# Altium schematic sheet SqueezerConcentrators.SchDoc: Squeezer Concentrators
size C; Organization: LIGO Laboratory; Address1: California Institute of Technology; Address2: Massachusetts Institute of Technology; SheetNumber: 34; SheetTotal: 37; DrawnBy: R.  Abbott; Engineer: R.  Abbott; PageSetup: Record=PageOptions¦CenterHorizontal=True¦CenterVertical=True¦PrintScale=1.09¦XCorrection=1.00¦YCorrection=1.00¦PrintKind=0¦BorderSize=5000000¦LeftOffset=0¦BottomOffset=0¦Orientation=2¦PaperLength=1000¦PaperWidth=1000¦Scale=100¦PaperSource=7¦PrintQuality=-4¦MediaType=1¦DitherType=10¦PaperKind=11x17¦PrintScaleMode=1
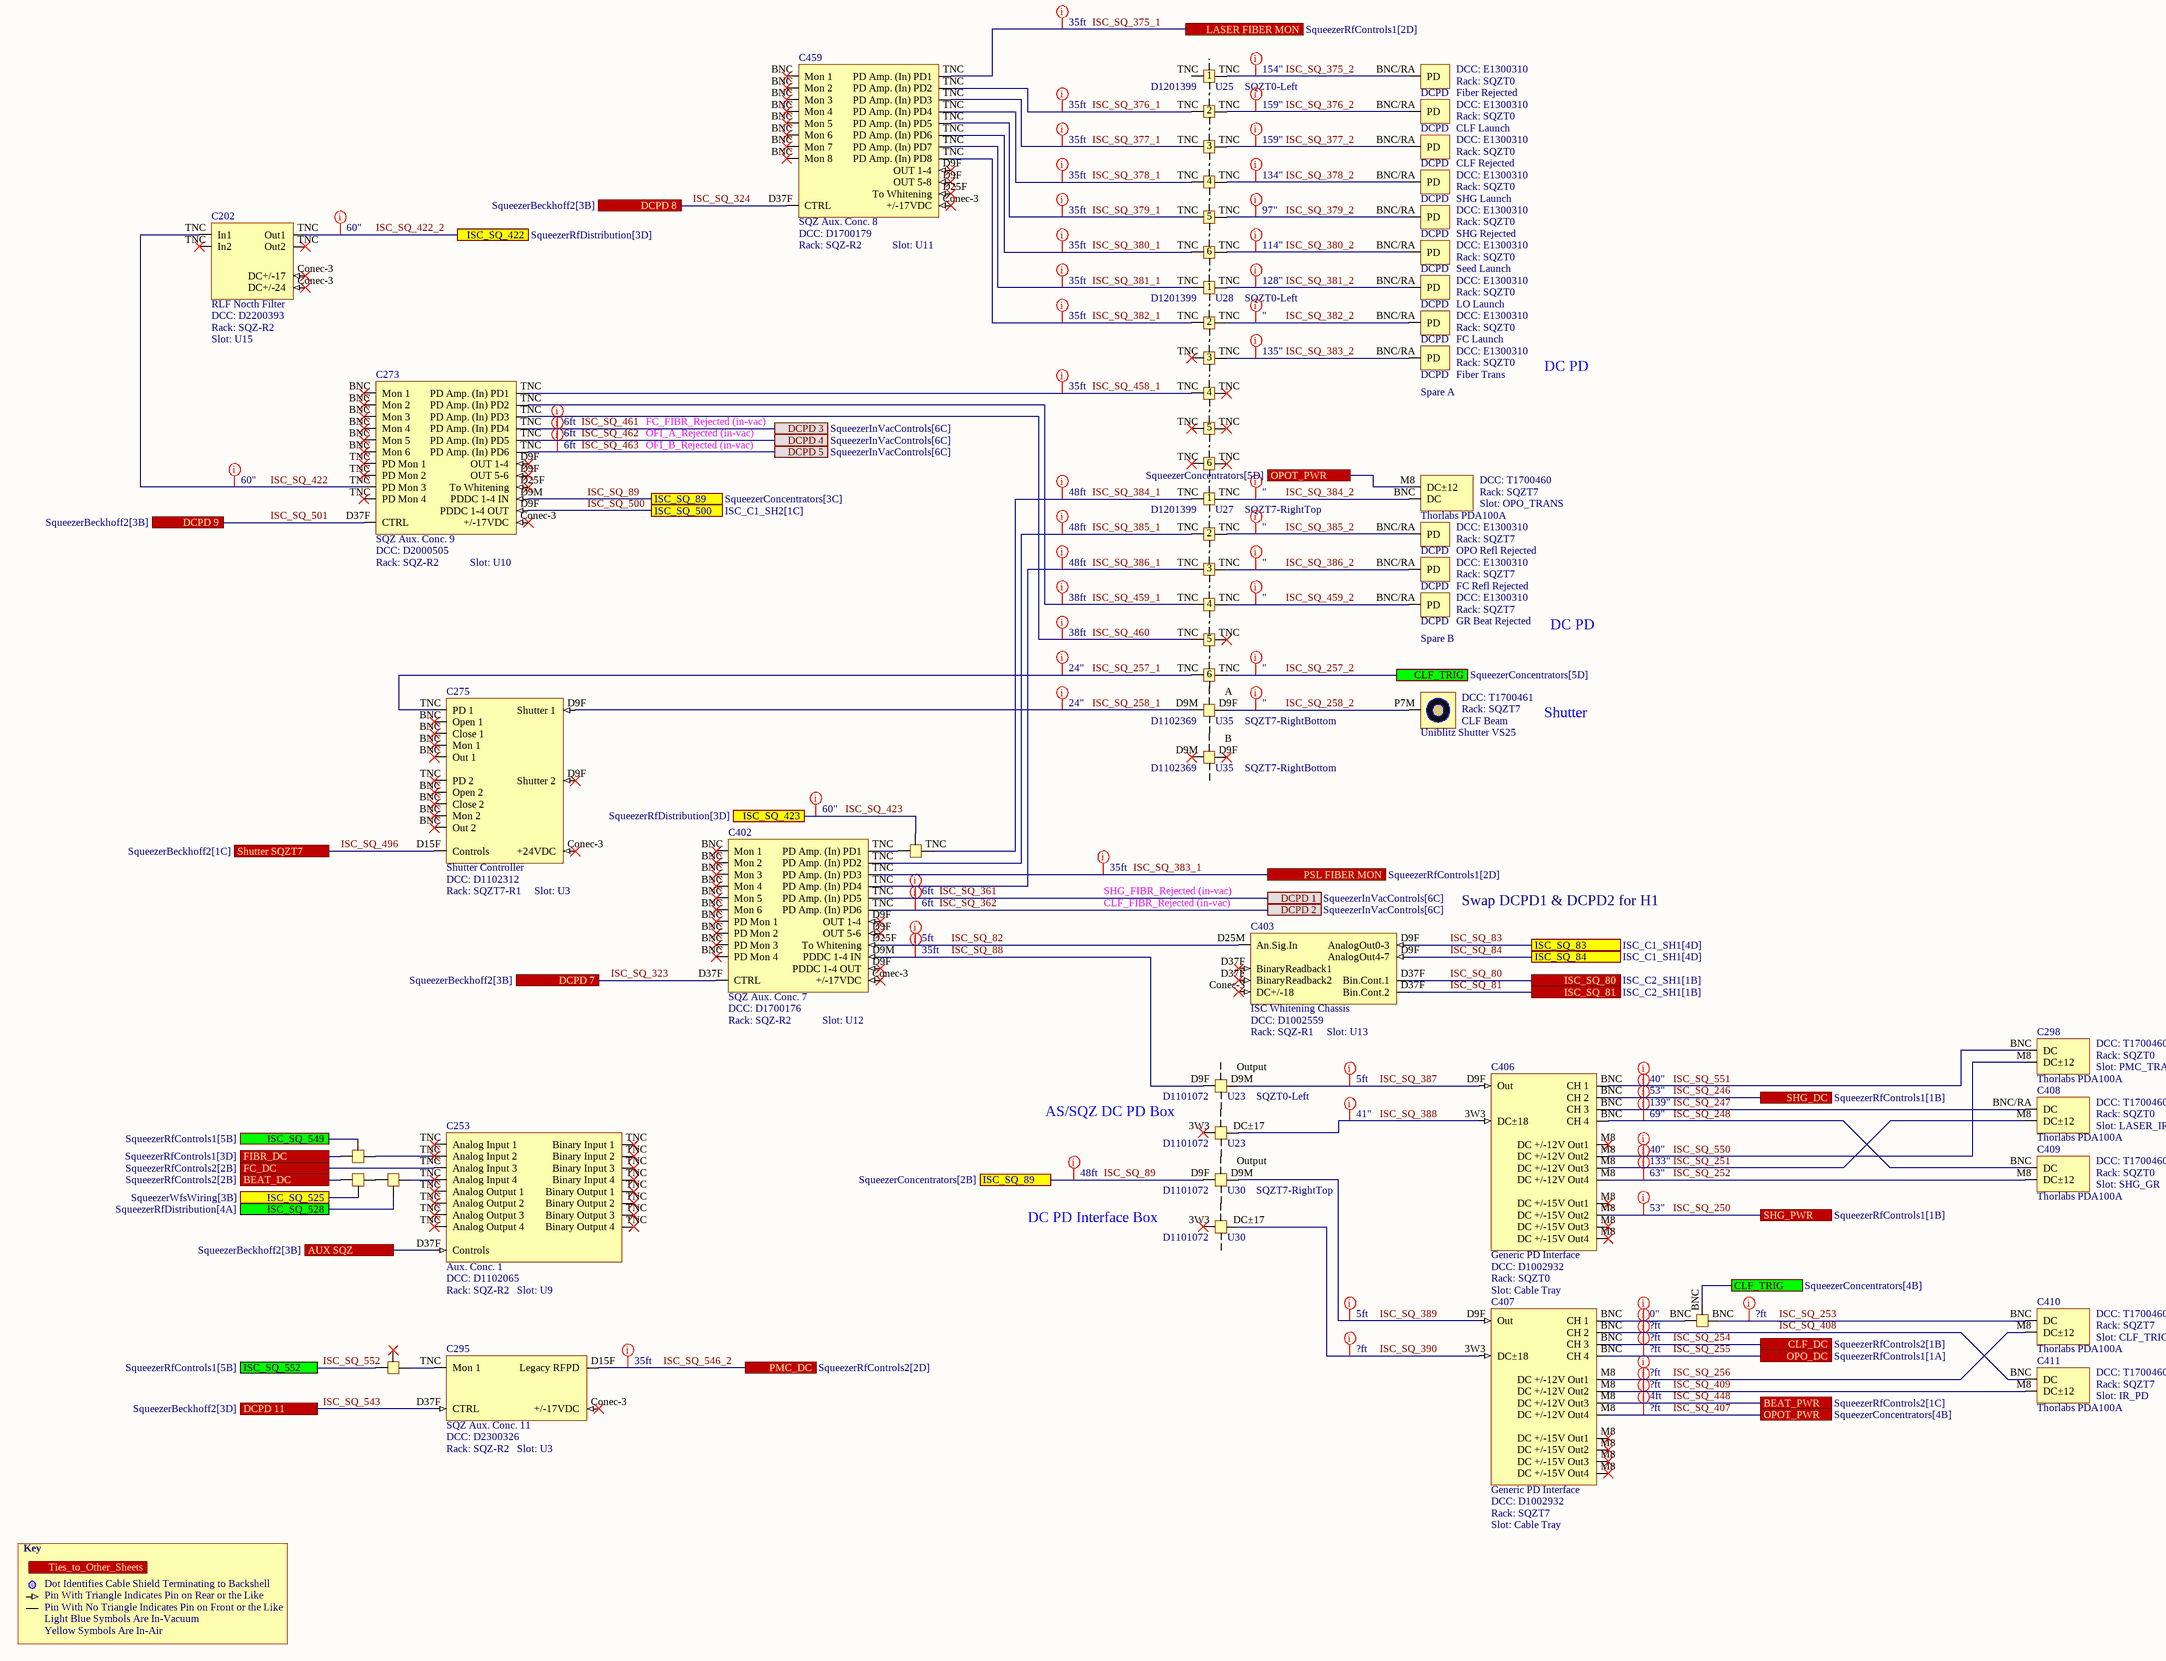
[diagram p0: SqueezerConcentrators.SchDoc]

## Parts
C202  RLF Nocth Filter  DCC: D2200393  Rack: SQZ-R2  Slot: U15
C235  DCPD  DCC: E1300310  Rack: SQZT0  Slot: FC Launch
C253  Aux. Conc. 1  DCC: D1102065  Rack: SQZ-R2  Slot: U9
C255  DCPD  DCC: E1300310  Rack: SQZT7  Slot: FC Refl Rejected
C256  DCPD  DCC: E1300310  Rack: SQZT7  Slot: GR Beat Rejected
C271  Tee  (value not drawn)
C273  SQZ Aux. Conc. 9  DCC: D2000505  Rack: SQZ-R2  Slot: U10
C275  Shutter Controller  DCC: D1102312  Rack: SQZT7-R1  Slot: U3
C283  Tee  (value not drawn)
C284  Tee  (value not drawn)
C295  SQZ Aux. Conc. 11  DCC: D2300326  Rack: SQZ-R2  Slot: U3
C297  Tee  (value not drawn)
C298  Thorlabs PDA100A  DCC: T1700460  Rack: SQZT0  Slot: PMC_TRANS
C315  Tee  (value not drawn)
C387  DCC: D1201399  Rack: SQZT0-Left  Slot: U25  (hidden comment: Patch Panel DCPD)  (parts A,B,C,D,E,F of 6)
C388  DCC: D1201399  Rack: SQZT0-Left  Slot: U28  (hidden comment: Patch Panel DCPD)  (parts A,B,C,D,E,F of 6)
C389  DCC: D1201399  Rack: SQZT7-RightTop  Slot: U27  (hidden comment: Patch Panel DCPD)  (parts A,B,C,D,E,F of 6)
C390  DCC: D1102369  Rack: SQZT7-RightBottom  Slot: U35  (hidden comment: Patch Panel Uniblitz Shutters)  (parts A,B of 2)
C391  DCPD  DCC: E1300310  Rack: SQZT0  Slot: Fiber Rejected
C392  DCPD  DCC: E1300310  Rack: SQZT0  Slot: CLF Launch
C393  DCPD  DCC: E1300310  Rack: SQZT0  Slot: CLF Rejected
C394  DCPD  DCC: E1300310  Rack: SQZT0  Slot: SHG Launch
C395  DCPD  DCC: E1300310  Rack: SQZT0  Slot: SHG Rejected
C396  DCPD  DCC: E1300310  Rack: SQZT0  Slot: Seed Launch
C397  DCPD  DCC: E1300310  Rack: SQZT0  Slot: LO Launch
C398  DCPD  DCC: E1300310  Rack: SQZT0  Slot: Fiber Trans
C399  Thorlabs PDA100A  DCC: T1700460  Rack: SQZT7  Slot: OPO_TRANS
C400  DCPD  DCC: E1300310  Rack: SQZT7  Slot: OPO Refl Rejected
C401  Uniblitz Shutter VS25  DCC: T1700461  Rack: SQZT7  Slot: CLF Beam
C402  SQZ Aux. Conc. 7  DCC: D1700176  Rack: SQZ-R2  Slot: U12
C403  ISC Whitening Chassis  DCC: D1002559  Rack: SQZ-R1  Slot: U13
C404  DCC: D1101072  Rack: SQZT0-Left  Slot: U23  (hidden comment: Patch Panel DCPD Interface)  (parts A,B of 2)
C405  DCC: D1101072  Rack: SQZT7-RightTop  Slot: U30  (hidden comment: Patch Panel DCPD Interface)  (parts A,B of 2)
C406  Generic PD Interface  DCC: D1002932  Rack: SQZT0  Slot: Cable Tray
C407  Generic PD Interface  DCC: D1002932  Rack: SQZT7  Slot: Cable Tray
C408  Thorlabs PDA100A  DCC: T1700460  Rack: SQZT0  Slot: LASER_IR
C409  Thorlabs PDA100A  DCC: T1700460  Rack: SQZT0  Slot: SHG_GR
C410  Thorlabs PDA100A  DCC: T1700460  Rack: SQZT7  Slot: CLF_TRIG
C411  Thorlabs PDA100A  DCC: T1700460  Rack: SQZT7  Slot: IR_PD
C459  SQZ Aux. Conc. 8  DCC: D1700179  Rack: SQZ-R2  Slot: U11
C467  Tee  (value not drawn)

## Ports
AUX SQZ (see SqueezerBeckhoff2[3B]), BEAT_DC (see SqueezerRfControls2[2B]), BEAT_PWR (see SqueezerRfControls2[1C]), CLF_DC (see SqueezerRfControls2[1B]), CLF_TRIG (see SqueezerConcentrators[4B]), CLF_TRIG (see SqueezerConcentrators[5D]), DCPD 1 (see SqueezerInVacControls[6C]), DCPD 2 (see SqueezerInVacControls[6C]), DCPD 3 (see SqueezerInVacControls[6C]), DCPD 4 (see SqueezerInVacControls[6C]), DCPD 5 (see SqueezerInVacControls[6C]), DCPD 7 (see SqueezerBeckhoff2[3B]), DCPD 8 (see SqueezerBeckhoff2[3B]), DCPD 9 (see SqueezerBeckhoff2[3B]), DCPD 11 (see SqueezerBeckhoff2[3D]), FC_DC (see SqueezerRfControls2[2B]), FIBR_DC (see SqueezerRfControls1[3D]), ISC_SQ_80 (see ISC_C2_SH1[1B]), ISC_SQ_81 (see ISC_C2_SH1[1B]), ISC_SQ_83 (see ISC_C1_SH1[4D]), ISC_SQ_84 (see ISC_C1_SH1[4D]), ISC_SQ_89 (see SqueezerConcentrators[2B]), ISC_SQ_89 (see SqueezerConcentrators[3C]), ISC_SQ_422 (see SqueezerRfDistribution[3D]), ISC_SQ_423 (see SqueezerRfDistribution[3D]), ISC_SQ_500 (see ISC_C1_SH2[1C]), ISC_SQ_525 (see SqueezerWfsWiring[3B]), ISC_SQ_528 (see SqueezerRfDistribution[4A]), ISC_SQ_549 (see SqueezerRfControls1[5B]), ISC_SQ_552 (see SqueezerRfControls1[5B]), LASER FIBER MON (see SqueezerRfControls1[2D]), OPO_DC (see SqueezerRfControls1[1A]), OPOT_PWR (see SqueezerConcentrators[4B]), OPOT_PWR (see SqueezerConcentrators[5D]), PMC_DC (see SqueezerRfControls2[2D]), PSL FIBER MON (see SqueezerRfControls1[2D]), SHG_DC (see SqueezerRfControls1[1B]), SHG_PWR (see SqueezerRfControls1[1B]), Shutter SQZT7 (see SqueezerBeckhoff2[1C]), Ties_to_Other_Sheets

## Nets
AUX SQZ: C253.D37F(Controls) ; port AUX SQZ
BEAT_DC: C467.TNC ; port BEAT_DC
FC_DC: C253.TNC(Analog_Input_3) ; port FC_DC
FIBR_DC: C297.TNC ; port FIBR_DC
ISC_SQ_80: C403.D37F(BinaryReadback1) ; port ISC_SQ_80
ISC_SQ_81: C403.D37F(Bin.Cont.2) ; port ISC_SQ_81
ISC_SQ_82: C402.D25F(To_Whitening) C403.D25M(An.Sig.In)
ISC_SQ_83: C403.D9F(AnalogOut0-3) ; port ISC_SQ_83
ISC_SQ_84: C403.D9F(AnalogOut4-7) ; port ISC_SQ_84
ISC_SQ_88: C402.D9M(PDDC_1-4_IN) C404.D9F(Output)
ISC_SQ_89: C273.D9M(PDDC_1-4_IN) C405.D9F(Output) ; port ISC_SQ_89
ISC_SQ_246: C406.BNC(CH_2) ; port SHG_DC
ISC_SQ_247: C406.BNC(CH_3) C408.BNC/RA(DC)
ISC_SQ_248: C406.BNC(CH_4) C409.BNC(DC)
ISC_SQ_250: C406.M8(DC_+/-15V_Out2) ; port SHG_PWR
ISC_SQ_251: C406.M8(DC_+/-12V_Out3) C408.M8(DC±12)
ISC_SQ_252: C406.M8(DC_+/-12V_Out4) C409.M8(DC±12)
ISC_SQ_253: C271.BNC C410.BNC(DC)
ISC_SQ_254: C407.BNC(CH_3) ; port CLF_DC
ISC_SQ_255: C407.BNC(CH_4) ; port OPO_DC
ISC_SQ_256: C407.M8(DC_+/-12V_Out1) C410.M8(DC±12)
ISC_SQ_257_1: C275.TNC(PD_1) C389.TNC
ISC_SQ_257_2: C271.BNC C389.TNC ; port CLF_TRIG
ISC_SQ_258_1: C275.D9F(Shutter_1) C390.D9M(Output)
ISC_SQ_258_2: C390.D9F(Output) C401.P7M
ISC_SQ_323: C402.D37F(CTRL) ; port DCPD 7
ISC_SQ_324: C459.D37F(CTRL) ; port DCPD 8
ISC_SQ_361: C402.TNC(PD_Amp._(In)_PD5) ; port DCPD 1
ISC_SQ_362: C402.TNC(PD_Amp._(In)_PD6) ; port DCPD 2
ISC_SQ_375_1: C459.TNC(PD_Amp._(In)_PD1) ; port LASER FIBER MON
ISC_SQ_375_2: C387.TNC C391.BNC/RA(PD)
ISC_SQ_376_1: C387.TNC C459.TNC(PD_Amp._(In)_PD2)
ISC_SQ_376_2: C387.TNC C392.BNC/RA(PD)
ISC_SQ_377_1: C387.TNC C459.TNC(PD_Amp._(In)_PD3)
ISC_SQ_377_2: C387.TNC C393.BNC/RA(PD)
ISC_SQ_378_1: C387.TNC C459.TNC(PD_Amp._(In)_PD4)
ISC_SQ_378_2: C387.TNC C394.BNC/RA(PD)
ISC_SQ_379_1: C387.TNC C459.TNC(PD_Amp._(In)_PD5)
ISC_SQ_379_2: C387.TNC C395.BNC/RA(PD)
ISC_SQ_380_1: C387.TNC C459.TNC(PD_Amp._(In)_PD6)
ISC_SQ_380_2: C387.TNC C396.BNC/RA(PD)
ISC_SQ_381_1: C388.TNC C459.TNC(PD_Amp._(In)_PD7)
ISC_SQ_381_2: C388.TNC C397.BNC/RA(PD)
ISC_SQ_382_1: C388.TNC C459.TNC(PD_Amp._(In)_PD8)
ISC_SQ_382_2: C235.BNC/RA(PD) C388.TNC
ISC_SQ_383_1: C402.TNC(PD_Amp._(In)_PD3) ; port PSL FIBER MON
ISC_SQ_383_2: C388.TNC C398.BNC/RA(PD)
ISC_SQ_384_1: C283.TNC C389.TNC
ISC_SQ_384_2: C389.TNC C399.BNC(DC)
ISC_SQ_385_1: C389.TNC C402.TNC(PD_Amp._(In)_PD2)
ISC_SQ_385_2: C389.TNC C400.BNC/RA(PD)
ISC_SQ_386_1: C389.TNC C402.TNC(PD_Amp._(In)_PD4)
ISC_SQ_386_2: C255.BNC/RA(PD) C389.TNC
ISC_SQ_387: C404.D9M(Output) C406.D9F(Out)
ISC_SQ_388: C404.3W3(DC±17) C406.3W3(DC±18)
ISC_SQ_389: C405.D9M(Output) C407.D9F(Out)
ISC_SQ_390: C405.3W3(DC±17) C407.3W3(DC±18)
ISC_SQ_407: C399.M8(DC±12) C407.M8(DC_+/-12V_Out4) ; port OPOT_PWR
ISC_SQ_408: C407.BNC(CH_2) C411.BNC(DC)
ISC_SQ_409: C407.M8(DC_+/-12V_Out2) C411.M8(DC±12)
ISC_SQ_422: C202.TNC(In1) C273.TNC(PD_Mon_3)
ISC_SQ_422_2: C202.TNC(Out1) ; port ISC_SQ_422
ISC_SQ_423: C283.TNC ; port ISC_SQ_423
ISC_SQ_448: C407.M8(DC_+/-12V_Out3) ; port BEAT_PWR
ISC_SQ_458_1: C273.TNC(PD_Amp._(In)_PD1) C388.TNC
ISC_SQ_459_1: C273.TNC(PD_Amp._(In)_PD2) C389.TNC
ISC_SQ_459_2: C256.BNC/RA(PD) C389.TNC
ISC_SQ_460: C273.TNC(PD_Amp._(In)_PD3) C389.TNC
ISC_SQ_461: C273.TNC(PD_Amp._(In)_PD4) ; port DCPD 3
ISC_SQ_462: C273.TNC(PD_Amp._(In)_PD5) ; port DCPD 4
ISC_SQ_463: C273.TNC(PD_Amp._(In)_PD6) ; port DCPD 5
ISC_SQ_496: C275.D15F(Controls) ; port Shutter SQZT7
ISC_SQ_500: C273.D9F(PDDC_1-4_OUT) ; port ISC_SQ_500
ISC_SQ_501: C273.D37F(CTRL) ; port DCPD 9
ISC_SQ_525: C467.TNC ; port ISC_SQ_525
ISC_SQ_528: C284.TNC ; port ISC_SQ_528
ISC_SQ_543: C295.D37F(CTRL) ; port DCPD 11
ISC_SQ_546_2: C295.D15F(Legacy_RFPD) ; port PMC_DC
ISC_SQ_549: C297.TNC ; port ISC_SQ_549
ISC_SQ_550: C298.M8(DC±12) C406.M8(DC_+/-12V_Out1)
ISC_SQ_551: C298.BNC(DC) C406.BNC(CH_1)
ISC_SQ_552: C315.TNC ; port ISC_SQ_552
NetC253_TNC: C253.TNC(Analog_Input_1) C297.TNC
NetC253_TNC: C253.TNC(Analog_Input_4) C284.TNC  [a separate net that carries the same name]
NetC271_BNC: C271.BNC C407.BNC(CH_1)
NetC283_TNC: C283.TNC C402.TNC(PD_Amp._(In)_PD1)
NetC284_TNC: C284.TNC C467.TNC
NetC295_TNC: C295.TNC(Mon_1) C315.TNC

Not connected (* = marked no-connect by the designer): C202 Conec-3(DC+/-17)*; C273 BNC(Mon_1)* Conec-3(+/-17VDC)* D25F(To_Whitening)*; C275 BNC(Open_1)* Conec-3(+24VDC)*; C295 Conec-3(+/-17VDC)*; C402 BNC(PD_Mon_1)* Conec-3(+/-17VDC)* D9F(PDDC_1-4_OUT)*; C403 Conec-3(DC+/-18)*; C459 BNC(Mon_1)* Conec-3(+/-17VDC)* D9F(OUT_1-4)* D25F(To_Whitening)*

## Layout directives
Length: 6ft: ISC_SQ_361, ISC_SQ_362, ISC_SQ_461, ISC_SQ_462, ISC_SQ_463
Length: 5ft: ISC_SQ_82, ISC_SQ_387, ISC_SQ_389
Length: 154": ISC_SQ_375_2
Length: 159": ISC_SQ_376_2, ISC_SQ_377_2
Length: 134": ISC_SQ_378_2
Length: 97": ISC_SQ_379_2
Length: 114": ISC_SQ_380_2
Length: 128": ISC_SQ_381_2
Length: 35ft: ISC_SQ_88, ISC_SQ_375_1, ISC_SQ_376_1, ISC_SQ_377_1, ISC_SQ_378_1, ISC_SQ_379_1, ISC_SQ_380_1, ISC_SQ_381_1, ISC_SQ_382_1, ISC_SQ_383_1, ISC_SQ_458_1, ISC_SQ_546_2
Length: 48ft: ISC_SQ_89, ISC_SQ_384_1, ISC_SQ_385_1, ISC_SQ_386_1
Length: ": ISC_SQ_257_2, ISC_SQ_258_2, ISC_SQ_382_2, ISC_SQ_384_2, ISC_SQ_385_2, ISC_SQ_386_2, ISC_SQ_459_2
Length: 135": ISC_SQ_383_2
Length: 41": ISC_SQ_388
Length: ?ft: ISC_SQ_253, ISC_SQ_254, ISC_SQ_255, ISC_SQ_256, ISC_SQ_390, ISC_SQ_407, ISC_SQ_408, ISC_SQ_409
Length: 40": ISC_SQ_550, ISC_SQ_551
Length: 53": ISC_SQ_246, ISC_SQ_250
Length: 139": ISC_SQ_247
Length: 69": ISC_SQ_248
Length: 133": ISC_SQ_251
Length: 63": ISC_SQ_252
Length: 0": NetC271_BNC
Length: 60": ISC_SQ_423
Length: 38ft: ISC_SQ_459_1, ISC_SQ_460
Length: 60'': ISC_SQ_422, ISC_SQ_422_2
Length: 24": ISC_SQ_257_1, ISC_SQ_258_1
Length: 4ft: ISC_SQ_448

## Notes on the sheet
- (near C398) Spare A
- DC PD
- FC_FIBR_Rejected (in-vac)
- OFI_A_Rejected (in-vac)
- OFI_B_Rejected (in-vac)
- (near C256) Spare B
- Shutter
- SHG_FIBR_Rejected (in-vac)
- (near C403) CLF_FIBR_Rejected (in-vac)
- Swap DCPD1 & DCPD2 for H1
- AS/SQZ DC PD Box
- DC PD Interface Box
- Key
- Dot Identifies Cable Shield Terminating to Backshell
- Pin With Triangle Indicates Pin on Rear or the Like
- Pin With No Triangle Indicates Pin on Front or the Like
- Light Blue Symbols Are In-Vacuum
- Yellow Symbols Are In-Air

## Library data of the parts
C202 = RLF Nocth Filter: Serial: Sxxxxxxx; System: ISC
C235 C255 C256 C391-C398 C400 = DCPD Unamplified: Unamplified DCPD; Serial: Sxxxxxxx; System: ISC
C253 = Aux. Conc. 1: Serial: Sxxxxxxx; System: ISC
C271 = TNC Tee: Tee (TNC); Serial: Sxxxxxxx; System: ISC; Rack: SQZT7
C273 = SQZ Aux. Conc. 9: Serial: Sxxxxxxx; System: ISC
C275 = Shutter Controller: Serial: Sxxxxxxx; System: ISC
C283 = TNC Tee: Tee (TNC); Serial: Sxxxxxxx; System: ISC; Rack: SQZ-R1; Slot: U18
C284 C297 C467 = TNC Tee: Tee (TNC); Serial: Sxxxxxxx; System: ISC; Rack: SQZ-R2; Slot: U9
C295 = SQZ Aux. Conc. 11: Serial: Sxxxxxxx; System: ISC
C298 C399 C408-C411 = Thorlabs PDA100A: Serial: Sxxxxxxx; System: ISC
C315 = TNC Tee: Tee (TNC); Serial: Sxxxxxxx; System: ISC; Rack: SQZ-R2; Slot: U3
C387-C389 = Patch Panel DCPD: Patch Panel (D1201399); Serial: Sxxxxxxx; System: ISC
C390 = Patch Panel Uniblitz Shutters: Patch Panel (D1102369); Serial: Sxxxxxxx; System: ISC
C401 = Uniblitz Shutter: Serial: Sxxxxxxx; System: ISC
C402 = SQZ Aux. Conc. 7: Serial: Sxxxxxxx; System: ISC
C403 = ISC Whitening: Serial: Sxxxxxxx
C404 C405 = Patch Panel DCPD Interface: Patch Panel (D1101072); Serial: Sxxxxxxx; System: ISC
C406 C407 = Generic PD Interface: Serial: Sxxxxxxx; System: ISC
C459 = SQZ Aux. Conc. 8: Serial: Sxxxxxxx; System: ISC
